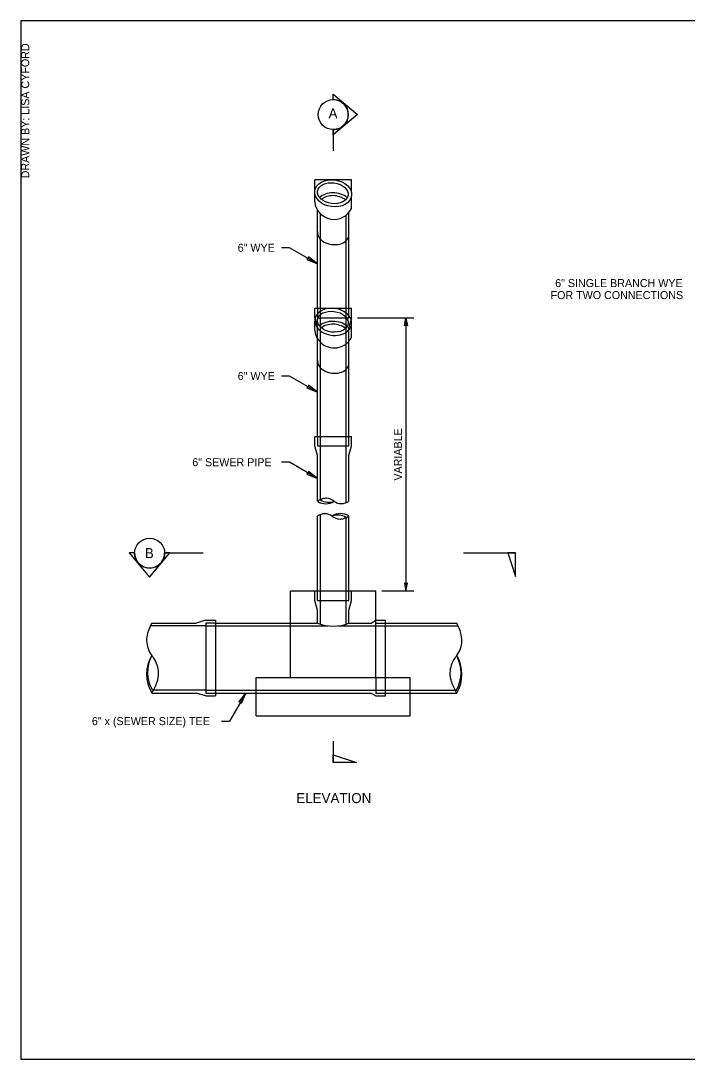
# Model space of a CAD drawing. Extents: x 99862 to 103151, y 100000 to 102076.
# Drawn here: x 99862 to 101195, y 100000 to 102076 of the extents above; entities that cross this region are included whole.
import ezdxf

# ---------------------------------------------------------------- set-up
doc = ezdxf.new("R2010")
doc.units = 0
for name, color, linetype in [('Level 1', 7, 'Continuous'), ('Level 15', 7, 'Continuous'), ('Level 20', 7, 'Continuous'), ('Level 6', 7, 'Continuous'), ('Level 60', 7, 'Continuous'), ('Level 62', 7, 'Continuous'), ('Level 9', 7, 'Continuous')]:
    doc.layers.add(name, color=color, linetype=linetype)

msp = doc.modelspace()

# ---------------------------------------------------------------- linework, layer by layer
at = {"layer": 'Level 1'}
for p, q in [((100401.3, 100935.8), (100572.1, 100935.8)), ((100401.3, 100762.9), (100401.3, 100935.8)), ((100572.1, 100762.9), (100572.1, 100935.8)), ((100333, 100762.9), (100640.4, 100762.9)), ((100333, 100686.1), (100333, 100762.9)), ((100640.4, 100686.1), (100640.4, 100762.9)), ((100333, 100686.1), (100640.4, 100686.1))]:
    msp.add_line(p, q, dxfattribs=at)
msp.add_lwpolyline([(99862, 99999.5), (103151, 99999.5), (103151, 102075.5), (99862, 102075.5)], close=True, dxfattribs=at)
at = {"layer": 'Level 15'}
for p, q in [((100399.1, 101621.8), (100383.1, 101621.8)), ((100455.4, 101589.3), (100399.1, 101621.8)), ((100535.6, 101481.6), (100648.1, 101481.6)), ((100632.1, 101481.6), (100632.1, 100935.8)), ((100399.1, 101365.3), (100383.1, 101365.3)), ((100455.4, 101332.8), (100399.1, 101365.3)), ((100399.1, 101193), (100383.1, 101193)), ((100455.4, 101160.5), (100399.1, 101193)), ((100584.1, 100935.8), (100648.1, 100935.8)), ((100311.8, 100731.6), (100279.3, 100675.4)), ((100263.3, 100675.4), (100279.3, 100675.4))]:
    msp.add_line(p, q, dxfattribs=at)
for points in [[(100455.4, 101589.3), (100437.2, 101603.3), (100436.6, 101600.2), (100434.2, 101598.2)], [(100632.1, 101481.6), (100635.1, 101465.9), (100632.1, 101466.6), (100629, 101465.9)], [(100455.4, 101332.8), (100437.2, 101346.8), (100436.6, 101343.7), (100434.2, 101341.6)], [(100455.4, 101160.5), (100437.2, 101174.5), (100436.6, 101171.4), (100434.2, 101169.4)], [(100632.1, 100935.8), (100635.1, 100951.5), (100632.1, 100950.8), (100629, 100951.5)], [(100311.8, 100731.6), (100303, 100710.4), (100300.9, 100712.8), (100297.8, 100713.4)]]:
    msp.add_lwpolyline(points, close=True, dxfattribs=at)
at = {"layer": 'Level 6'}
for p, q in [((100523.6, 101757.8), (100449.8, 101757.8)), ((100449.8, 101713.4), (100449.8, 101732.1)), ((100523.6, 101700.2), (100523.6, 101725.8)), ((100455.4, 101615.2), (100455.4, 101697.7)), ((100455.4, 101500.8), (100455.4, 101697)), ((100461.1, 101117.9), (100461.1, 101689.9)), ((100512.3, 101112.2), (100512.3, 101686.5)), ((100517.9, 101500.8), (100517.9, 101691.8)), ((100517.9, 101615.2), (100517.9, 101691.8)), ((100449.8, 101500.8), (100523.6, 101500.8)), ((100449.8, 101481.6), (100449.8, 101500.8)), ((100523.6, 101481.7), (100523.6, 101500.8)), ((100449.8, 101481.6), (100455.4, 101462.4)), ((100449.8, 101456.5), (100449.8, 101475.2)), ((100523.6, 101481.7), (100517.9, 101462.4)), ((100455.4, 101244.7), (100455.4, 101462.4)), ((100517.9, 101244.7), (100517.9, 101462.4)), ((100523.6, 101443.2), (100523.6, 101468.9)), ((100449.8, 101244.7), (100523.6, 101244.7)), ((100449.8, 101225.5), (100449.8, 101244.7)), ((100523.6, 101225.5), (100523.6, 101244.7)), ((100455.4, 101206.3), (100449.8, 101225.5)), ((100455.4, 101114.8), (100455.4, 101206.3)), ((100517.9, 101206.3), (100523.6, 101225.5)), ((100517.9, 101114.8), (100517.9, 101206.3)), ((100455.4, 100935.8), (100455.4, 101085.4)), ((100461.1, 100869.3), (100461.1, 101087.5)), ((100512.3, 100869.3), (100512.3, 101082.3)), ((100517.9, 100935.8), (100517.9, 101085.4)), ((100449.8, 100916.6), (100449.8, 100935.8)), ((100455.4, 100916.6), (100455.4, 100935.8)), ((100517.9, 100916.6), (100517.9, 100935.8)), ((100523.6, 100916.6), (100523.6, 100935.8)), ((100455.4, 100897.4), (100449.8, 100916.6)), ((100455.4, 100916.6), (100517.9, 100916.6)), ((100517.9, 100897.4), (100523.6, 100916.6)), ((100455.4, 100871.4), (100455.4, 100897.4)), ((100517.9, 100871.4), (100517.9, 100897.4)), ((100232, 100877.1), (100212.8, 100871.4)), ((100232, 100877.1), (100251.2, 100877.1)), ((100251.2, 100877.1), (100251.2, 100726)), ((100572.1, 100877.1), (100591.3, 100877.1)), ((100591.3, 100762.8), (100591.3, 100877.1)), ((100232, 100865.8), (100121, 100865.8)), ((100123.9, 100871.4), (100212.8, 100871.4)), ((100232, 100865.8), (100476.8, 100865.8)), ((100251.2, 100871.4), (100401.3, 100871.4)), ((100401.3, 100871.4), (100455.4, 100871.4)), ((100496.6, 100865.8), (100572.1, 100865.8)), ((100572.1, 100871.4), (100591.3, 100871.4)), ((100572.1, 100865.8), (100736.5, 100865.8)), ((100591.3, 100871.4), (100733.7, 100871.4)), ((100591.1, 100726), (100591.1, 100762.9)), ((100123.9, 100731.6), (100212.8, 100731.6)), ((100232, 100737.3), (100127.3, 100737.3)), ((100232, 100726), (100212.8, 100731.6)), ((100232, 100737.3), (100571.9, 100737.3)), ((100251.2, 100731.6), (100333, 100731.6)), ((100333, 100731.6), (100562.3, 100731.6)), ((100562.3, 100731.6), (100571.9, 100726)), ((100571.9, 100737.3), (100730.3, 100737.3)), ((100571.9, 100731.6), (100640.4, 100731.6)), ((100640.4, 100731.6), (100733.7, 100731.6)), ((100232, 100726), (100251.2, 100726)), ((100571.9, 100726), (100591.1, 100726))]:
    msp.add_line(p, q, dxfattribs=at)
for points in [[(100450.1, 101735.3), (100449.8, 101737.8), (100449.8, 101757.8)], [(100523.1, 101732.7), (100523.6, 101737.8), (100523.6, 101757.8)], [(100455.4, 101500.8), (100455.4, 101481.6), (100517.9, 101481.6), (100517.9, 101500.8)], [(100455.4, 101244.7), (100455.4, 101225.5), (100517.9, 101225.5), (100517.9, 101244.7)], [(100517.9, 100871.4), (100562.5, 100871.4), (100572.1, 100877.1)], [(100251.2, 100871.4), (100232, 100871.4), (100232, 100731.6), (100251.2, 100731.6)], [(100572.1, 100762.9), (100571.9, 100731.6)]]:
    msp.add_lwpolyline(points, dxfattribs=at)
for centre, radius, start, end in [((100488.6, 101717.6), 39.1, 186.1678, 333.5053), ((100488.6, 101460.6), 39.1, 186.1172, 211.6898), ((100488.6, 101460.6), 39.1, 211.7844, 318.3402), ((100488.6, 101460.6), 39.1, 318.6495, 333.5053), ((100479.3, 101078.3), 43.6, 108.5999, 123.1818), ((100472.1, 101142.1), 32, 238.5089, 301.2615), ((100461.2, 101117.7), 0.236, 124.6475, 249.4332), ((100477.9, 101145.3), 32.4, 238.9203, 289.6128), ((100472.9, 101097.3), 23.6, 88.7194, 108.5999), ((100470.9, 101092.3), 28.7, 51.494, 84.9542), ((100502.5, 101133.4), 23.2, 233.5715, 269.0004), ((100502.3, 101134.5), 24.3, 269.5848, 285.7783), ((100497, 101153.2), 43.8, 285.7783, 298.5745), ((100476.4, 101047), 43.8, 105.7783, 118.5745), ((100471.1, 101065.7), 24.3, 89.5848, 105.7783), ((100470.6, 101067), 23, 53.0711, 88.4999), ((100501.2, 101058.2), 32, 58.502, 121.5471), ((100495.5, 101054.8), 32.6, 59.134, 109.8266), ((100502.3, 101108.1), 28.8, 231.9346, 265.3948), ((100500.5, 101102.9), 23.6, 268.7194, 288.5999), ((100494.1, 101121.9), 43.6, 288.5999, 303.1818), ((100512.2, 101082.5), 0.236, 304.6475, 69.4332), ((100209.9, 100824.6), 98, 151.4696, 164.2217), ((100486.7, 100946.6), 81.4, 247.423, 292.577), ((100647.6, 100824.6), 98, 15.7783, 28.5304), ((100167.9, 100836.5), 54.3, 164.2217, 180.4152), ((100165.1, 100837.5), 51.5, 181.5001, 216.9289), ((100692.5, 100837.5), 51.5, 323.0711, 358.4999), ((100689.6, 100836.5), 54.3, 359.5848, 15.7783), ((100184.9, 100769.1), 71.6, 148.4529, 211.498), ((100186.9, 100773.1), 71.3, 152.0249, 209.9049), ((100165.5, 100836.5), 51.3, 215.8440416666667, 215.84404281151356), ((100165.3, 100833.6), 49.4, 213.2131, 220.8743), ((100083.9, 100770.7), 53.6, 1.2806, 34.7408), ((100773.7, 100770.7), 53.6, 145.2592, 178.7194), ((100692.3, 100833.6), 49.4, 319.1257, 326.7869), ((100671, 100772.4), 71.3, 330.8017, 28.595), ((100672.6, 100769.1), 71.6, 328.502, 31.5471), ((100084.7, 100770.7), 52.7, 341.4001, 1.2806), ((100772.8, 100770.7), 52.7, 178.7194, 198.5999), ((100042.3, 100785), 97.5, 326.8182, 341.4001), ((100815.3, 100785), 97.5, 198.5999, 213.1818), ((100126.3, 100738.3), 1.44, 214.9799, 321.0453), ((100731.7, 100738.3), 1.74, 205.2175, 335.825)]:
    msp.add_arc(centre, radius, start, end, dxfattribs=at)
for centre, major_axis, ratio in [((100486.7, 101730.6), (-36.7, 4.7), 0.727568), ((100486, 101730.8), (-30.6, 4), 0.673708), ((100486, 101473.9), (-30.6, 4), 0.673708)]:
    msp.add_ellipse(centre, major_axis=major_axis, ratio=ratio, dxfattribs=at)
for centre, major_axis, ratio, start_param, end_param in [((100488.9, 101704.9), (-36.2, 4.7), 0.724086, 4.008998, 5.750085), ((100488.9, 101704.9), (-30.6, 4), 0.673708, 3.972542, 5.783316), ((100486.6, 101649.4), (-31.1, 4), 0.679228, 6.283122, 9.42473), ((100486.7, 101473.6), (-36.7, 4.7), 0.727568, 3.50321, 6.228678), ((100486.7, 101473.6), (-36.7, 4.7), 0.727568, 6.228678, 6.931104), ((100486.7, 101473.6), (-36.7, 4.7), 0.727568, 2.675073, 3.477856), ((100486.7, 101473.6), (-36.7, 4.7), 0.727568, 0.647918, 2.675073), ((100488.9, 101448), (-36.2, 4.7), 0.724086, 4.008998, 5.750085), ((100488.9, 101448), (-30.6, 4), 0.673708, 3.972542, 5.783316), ((100486.6, 101392.4), (-31.1, 4), 0.679228, 6.283122, 9.42473)]:
    msp.add_ellipse(centre, major_axis=major_axis, ratio=ratio, start_param=start_param, end_param=end_param, dxfattribs=at)
at = {"layer": 'Level 60'}
msp.add_line((99862, 99999.5), (99862, 99999.5), dxfattribs=at)
at = {"layer": 'Level 9'}
for p, q in [((100486.7, 101918), (100486.7, 101928.6)), ((100486.7, 101928.6), (100535.1, 101888)), ((100535.1, 101888), (100486.7, 101847.4)), ((100486.7, 101847.4), (100486.7, 101858)), ((100486.7, 101858), (100486.7, 101815.6)), ((100089.5, 101011.7), (100078.9, 101011.7)), ((100078.9, 101011.7), (100119.5, 100963.2)), ((100119.5, 100963.2), (100160.1, 101011.7)), ((100160.1, 101011.7), (100149.5, 101011.7)), ((100151.1, 101011.7), (100226.5, 101011.7)), ((100747.2, 101011.7), (100851.1, 101011.7)), ((100486.7, 100635.3), (100486.7, 100592.8))]:
    msp.add_line(p, q, dxfattribs=at)
for points in [[(100835.6, 101011.7), (100851.1, 100964.8), (100851.1, 101011.7)], [(100486.7, 100608.3), (100533.6, 100592.8), (100486.7, 100592.8)]]:
    msp.add_lwpolyline(points, close=True, dxfattribs=at)
for centre in [(100486.7, 101888), (100119.7, 101011.1)]:
    msp.add_circle(centre, 30, dxfattribs=at)
for centre, start, end in [((100486.7, 101888), 269.9978, 90.0022), ((100119.5, 101011.7), 179.9978, 0.0022)]:
    msp.add_arc(centre, 30, start, end, dxfattribs=at)

# ---------------------------------------------------------------- texts
at = {"layer": 'Level 20'}
for s, height, p in [('A', 20, (100477.4, 101880.4)), ('6" SINGLE BRANCH WYE', 16, (100930.5, 101543.1)), ('FOR TWO CONNECTIONS', 16, (100921.3, 101519.1)), ('6" WYE', 16, (100295.8, 101357.3)), ('6" SEWER PIPE', 16, (100204.9, 101185)), ('B', 20, (100110.1, 101001.3)), ('6" x (SEWER SIZE) TEE', 16, (100004.2, 100667.4)), ('ELEVATION', 20, (100412.9, 100511.6))]:
    msp.add_text(s, height=height, dxfattribs=at).set_placement(p)
for s, rotation, p in [('6" WYE', 360, (100295.8, 101613.8)), ('VARIABLE', 90, (100624.1, 101156.2))]:
    msp.add_text(s, height=16, rotation=rotation, dxfattribs=at).set_placement(p)
at = {"layer": 'Level 62'}
msp.add_text('DRAWN BY: LISA CYFORD', height=16, rotation=90, dxfattribs=at).set_placement((99879, 101760.5))

doc.saveas('drawing.dxf')
